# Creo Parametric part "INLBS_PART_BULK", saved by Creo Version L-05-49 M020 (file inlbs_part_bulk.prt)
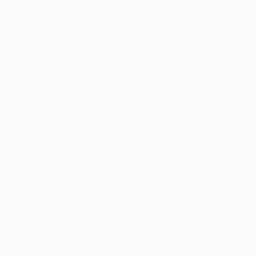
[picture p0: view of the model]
Units: Inch lbm Second (Pro/E Default); INCH, POUND, SECS

Other parameters: BOM_REPORT_QUANTITY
